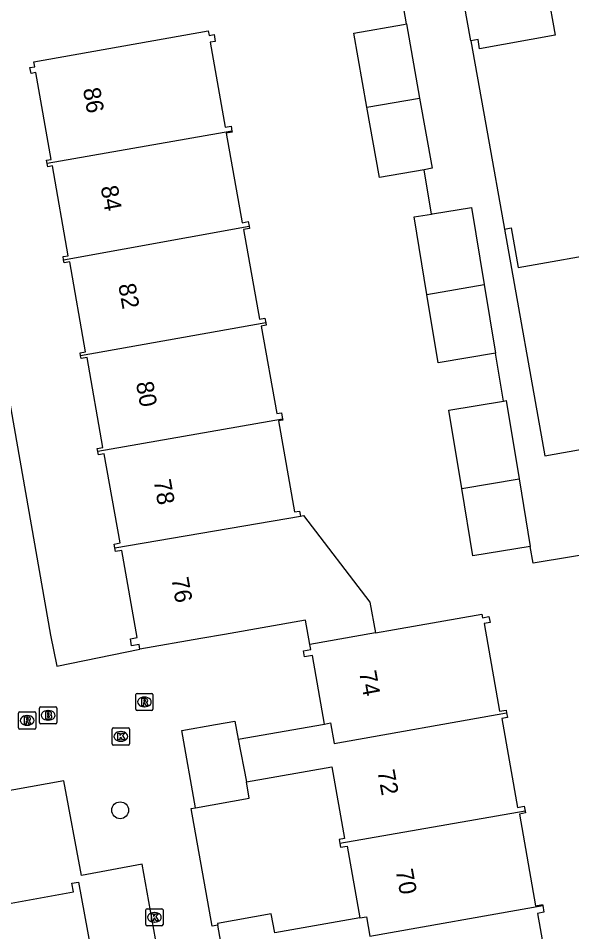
# Model space of a CAD drawing. Extents: x 157793 to 159380, y 380882 to 382313.
# Drawn here: x 158380 to 158412.2, y 381373.4 to 381426.5 of the extents above; entities that cross this region are included whole.
import ezdxf

# ---------------------------------------------------------------- set-up
doc = ezdxf.new("R2010")
doc.units = 0
for name, color, linetype in [('IMGEO_Boom', 7, 'Continuous'), ('IMGEO_Brandkraan', 7, 'Continuous'), ('IMGEO_Kolk', 7, 'Continuous'), ('IMGEO_Pand', 7, 'Continuous'), ('IMGEO_Pand_nummerreeks', 7, 'Continuous'), ('IMGEO_Rioolput', 7, 'Continuous'), ('IMGEO_Voetpad_open', 7, 'Continuous')]:
    doc.layers.add(name, color=color, linetype=linetype)

msp = doc.modelspace()

# ---------------------------------------------------------------- linework, layer by layer
at = {"layer": 'IMGEO_Boom'}
msp.add_circle((158385.911, 381380.479), 0.489, dxfattribs=at)
at = {"layer": 'IMGEO_Brandkraan'}
for p, q in [((158381.221, 381385.571), (158381.221, 381386.423)), ((158381.296, 381386.497), (158382.148, 381386.497)), ((158381.709, 381386.277), (158381.734, 381386.277)), ((158382.222, 381386.423), (158382.222, 381385.571)), ((158381.732, 381385.717), (158381.707, 381385.717)), ((158382.148, 381385.497), (158381.296, 381385.497))]:
    msp.add_line(p, q, dxfattribs=at)
for points in [[(158381.221, 381385.571), (158381.221, 381386.423)], [(158381.296, 381386.497), (158382.148, 381386.497)], [(158381.569, 381386.197), (158381.569, 381385.797), (158381.782, 381385.797)], [(158381.8, 381386.197), (158381.569, 381386.197)], [(158381.748, 381386.116), (158381.694, 381386.116), (158381.694, 381386.04)], [(158382.222, 381386.423), (158382.222, 381385.571)], [(158381.694, 381386.04), (158381.747, 381386.04)], [(158381.756, 381385.964), (158381.694, 381385.964), (158381.694, 381385.883)], [(158381.694, 381385.883), (158381.756, 381385.883)], [(158382.148, 381385.497), (158381.296, 381385.497)]]:
    msp.add_lwpolyline(points, dxfattribs=at)
for centre, radius, start, end in [((158381.298, 381386.421), 0.0765, 91.552, 178.448), ((158381.298, 381386.421), 0.0765, 91.552, 178.448), ((158381.749, 381386.078), 0.0379, 267.8285, 90.9355), ((158381.804, 381386.052), 0.145, 59.4692, 91.5367), ((158381.829, 381386.099), 0.0922, 285.5137, 58.1501), ((158382.146, 381386.421), 0.0765, 1.552, 88.448), ((158382.146, 381386.421), 0.0765, 1.552, 88.448), ((158381.757, 381385.923), 0.0404, 269.8759, 90.5077), ((158381.788, 381386.048), 0.251, 268.6676, 293.5347), ((158381.834, 381385.907), 0.105, 301.3115, 78.989), ((158381.298, 381385.573), 0.0765, 181.552, 268.448), ((158381.298, 381385.573), 0.0765, 181.552, 268.448), ((158382.146, 381385.573), 0.0765, 271.552, 358.448), ((158382.146, 381385.573), 0.0765, 271.552, 358.448)]:
    msp.add_arc(centre, radius, start, end, dxfattribs=at)
for centre, major_axis, ratio, start_param, end_param in [((158381.708, 381385.997), (-0.387, 0.002), 0.722429, 4.712389, 7.853982), ((158381.733, 381385.997), (-0.39, 0.002), 0.717154, 1.570796, 4.712389)]:
    msp.add_ellipse(centre, major_axis=major_axis, ratio=ratio, start_param=start_param, end_param=end_param, dxfattribs=at)
at = {"layer": 'IMGEO_Kolk'}
for p, q in [((158385.45, 381384.343), (158385.45, 381385.195)), ((158385.525, 381385.269), (158386.377, 381385.269)), ((158385.938, 381385.049), (158385.963, 381385.049)), ((158386.451, 381385.195), (158386.451, 381384.343)), ((158386.377, 381384.269), (158385.525, 381384.269)), ((158385.961, 381384.489), (158385.936, 381384.489)), ((158387.405, 381373.829), (158387.405, 381374.681)), ((158387.48, 381374.755), (158388.332, 381374.755)), ((158387.893, 381374.535), (158387.918, 381374.535)), ((158388.406, 381374.681), (158388.406, 381373.829)), ((158387.916, 381373.975), (158387.891, 381373.975)), ((158388.332, 381373.755), (158387.48, 381373.755))]:
    msp.add_line(p, q, dxfattribs=at)
for points in [[(158385.45, 381384.343), (158385.45, 381385.195)], [(158385.525, 381385.269), (158386.377, 381385.269)], [(158386.451, 381385.195), (158386.451, 381384.343)], [(158385.771, 381384.969), (158385.894, 381384.969), (158385.894, 381384.818), (158386.024, 381384.969), (158386.188, 381384.969), (158386.042, 381384.818), (158386.195, 381384.569), (158386.043, 381384.569), (158385.958, 381384.733), (158385.894, 381384.666), (158385.894, 381384.569), (158385.771, 381384.569), (158385.771, 381384.969)], [(158386.377, 381384.269), (158385.525, 381384.269)], [(158387.405, 381373.829), (158387.405, 381374.681)], [(158387.48, 381374.755), (158388.332, 381374.755)], [(158387.726, 381374.455), (158387.849, 381374.455), (158387.849, 381374.304), (158387.979, 381374.455), (158388.143, 381374.455), (158387.997, 381374.304), (158388.15, 381374.055), (158387.998, 381374.055), (158387.913, 381374.219), (158387.849, 381374.152), (158387.849, 381374.055), (158387.726, 381374.055), (158387.726, 381374.455)], [(158388.406, 381374.681), (158388.406, 381373.829)], [(158388.332, 381373.755), (158387.48, 381373.755)]]:
    msp.add_lwpolyline(points, dxfattribs=at)
for centre, start, end in [((158385.527, 381385.193), 91.552, 178.448), ((158385.527, 381385.193), 91.552, 178.448), ((158386.375, 381385.193), 1.552, 88.448), ((158386.375, 381385.193), 1.552, 88.448), ((158385.527, 381384.345), 181.552, 268.448), ((158385.527, 381384.345), 181.552, 268.448), ((158386.375, 381384.345), 271.552, 358.448), ((158386.375, 381384.345), 271.552, 358.448), ((158387.482, 381374.679), 91.552, 178.448), ((158387.482, 381374.679), 91.552, 178.448), ((158388.33, 381374.679), 1.552, 88.448), ((158388.33, 381374.679), 1.552, 88.448), ((158387.482, 381373.831), 181.552, 268.448), ((158387.482, 381373.831), 181.552, 268.448), ((158388.33, 381373.831), 271.552, 358.448), ((158388.33, 381373.831), 271.552, 358.448)]:
    msp.add_arc(centre, 0.0765, start, end, dxfattribs=at)
for centre, major_axis, ratio, start_param, end_param in [((158385.937, 381384.769), (-0.387, 0.002), 0.722429, 4.712389, 7.853982), ((158385.962, 381384.769), (-0.39, 0.002), 0.717154, 1.570796, 4.712389), ((158387.892, 381374.255), (-0.387, 0.002), 0.722429, 4.712389, 7.853982), ((158387.917, 381374.255), (-0.39, 0.002), 0.717154, 1.570796, 4.712389)]:
    msp.add_ellipse(centre, major_axis=major_axis, ratio=ratio, start_param=start_param, end_param=end_param, dxfattribs=at)
at = {"layer": 'IMGEO_Pand'}
for points in [[(158410.323, 381430.524), (158411.216, 381425.529), (158406.827, 381424.744), (158406.731, 381425.281), (158406.31, 381425.206)], [(158400.269, 381421.344), (158399.508, 381425.651), (158402.397, 381426.162), (158402.574, 381426.193)], [(158402.574, 381426.193), (158403.335, 381421.883)], [(158381.668, 381418.075), (158381.635, 381418.26), (158381.9, 381418.306), (158381.007, 381423.363), (158380.726, 381423.313), (158380.666, 381423.652), (158380.949, 381423.702), (158380.898, 381423.987), (158391.038, 381425.778), (158391.083, 381425.525), (158391.374, 381425.576), (158391.445, 381425.174), (158391.155, 381425.122), (158392.028, 381420.18), (158392.362, 381420.239), (158392.411, 381419.963)], [(158406.31, 381425.206), (158407.278, 381419.793), (158408.266, 381414.262)], [(158400.269, 381421.344), (158403.335, 381421.883)], [(158403.335, 381421.883), (158404.057, 381417.798), (158403.598, 381417.717)], [(158403.598, 381417.717), (158400.991, 381417.256), (158400.269, 381421.344)], [(158392.411, 381419.963), (158381.668, 381418.075)], [(158392.411, 381419.963), (158392.423, 381419.894), (158392.087, 381419.835), (158393.006, 381414.633), (158393.366, 381414.697), (158393.414, 381414.429)], [(158382.623, 381412.48), (158382.591, 381412.66), (158382.889, 381412.713), (158381.967, 381417.935), (158381.701, 381417.888), (158381.668, 381418.075)], [(158404.022, 381415.138), (158404.088, 381415.149), (158406.354, 381415.522), (158407.091, 381411.048)], [(158403.754, 381410.459), (158403.011, 381414.972), (158404.022, 381415.138)], [(158382.623, 381412.48), (158393.414, 381414.429)], [(158393.414, 381414.429), (158393.438, 381414.292), (158393.096, 381414.231), (158394.015, 381409.03), (158394.334, 381409.086), (158394.384, 381408.805)], [(158408.266, 381414.262), (158408.662, 381414.333), (158409.075, 381412.023), (158414.559, 381413.003)], [(158383.614, 381406.904), (158383.583, 381407.077), (158383.904, 381407.134), (158382.981, 381412.36), (158382.654, 381412.302), (158382.623, 381412.48)], [(158403.754, 381410.459), (158407.091, 381411.048)], [(158407.091, 381411.048), (158407.751, 381407.041)], [(158407.751, 381407.041), (158404.408, 381406.49), (158403.754, 381410.459)], [(158394.384, 381408.805), (158383.614, 381406.904)], [(158394.384, 381408.805), (158394.406, 381408.678), (158394.123, 381408.628), (158395.023, 381403.537), (158395.295, 381403.585), (158395.36, 381403.217)], [(158384.617, 381401.33), (158384.584, 381401.515), (158384.906, 381401.572), (158383.984, 381406.793), (158383.644, 381406.733), (158383.614, 381406.904)], [(158405.784, 381399.177), (158405.032, 381403.744), (158408.207, 381404.266)], [(158408.207, 381404.266), (158408.375, 381404.294), (158409.124, 381399.747)], [(158395.36, 381403.217), (158384.617, 381401.33)], [(158395.36, 381403.217), (158395.371, 381403.157), (158395.121, 381403.113), (158396.056, 381397.822), (158396.352, 381397.875), (158396.405, 381397.577)], [(158385.607, 381395.735), (158385.568, 381395.956), (158385.903, 381396.015), (158384.987, 381401.204), (158384.65, 381401.144), (158384.617, 381401.33)], [(158405.784, 381399.177), (158409.124, 381399.747)], [(158409.124, 381399.747), (158409.772, 381395.813)], [(158409.772, 381395.813), (158406.429, 381395.262), (158405.784, 381399.177)], [(158385.607, 381395.735), (158396.405, 381397.577)], [(158396.405, 381397.577), (158396.576, 381397.607), (158400.447, 381392.573), (158400.761, 381390.791)], [(158387.065, 381389.835), (158387.016, 381390.113), (158386.576, 381390.035), (158386.504, 381390.442), (158386.905, 381390.513), (158386.01, 381395.58), (158385.646, 381395.515), (158385.607, 381395.735)], [(158396.949, 381390.117), (158396.698, 381391.537), (158391.989, 381390.705), (158390.596, 381390.459), (158387.065, 381389.835)], [(158400.761, 381390.791), (158401.873, 381390.987), (158406.957, 381391.885), (158406.995, 381391.669), (158407.37, 381391.735), (158407.431, 381391.387), (158407.086, 381391.326), (158407.985, 381386.237), (158408.361, 381386.303), (158408.389, 381386.142)], [(158400.761, 381390.791), (158396.949, 381390.117)], [(158397.798, 381385.49), (158397.094, 381389.475), (158396.637, 381389.394), (158396.575, 381389.748), (158397.001, 381389.823), (158396.949, 381390.117)], [(158397.798, 381385.49), (158398.147, 381385.552), (158398.366, 381384.369), (158408.389, 381386.142)], [(158408.389, 381386.142), (158408.438, 381385.867), (158408.109, 381385.809), (158409.02, 381380.647), (158409.425, 381380.718), (158409.475, 381380.43)], [(158390.299, 381380.625), (158389.505, 381385.119), (158391.453, 381385.463), (158392.591, 381385.664), (158392.778, 381384.603)], [(158392.778, 381384.603), (158397.798, 381385.49)], [(158392.778, 381384.603), (158393.256, 381382.134)], [(158393.256, 381382.134), (158398.228, 381383.012), (158398.965, 381378.839), (158398.648, 381378.783), (158398.688, 381378.555)], [(158390.299, 381380.625), (158393.425, 381381.178), (158393.256, 381382.134)], [(158378.738, 381381.484), (158378.983, 381380.14), (158378.017, 381379.963), (158378.668, 381376.395), (158378.931, 381374.956), (158383.201, 381375.735), (158383.109, 381376.239), (158383.488, 381376.308), (158384.184, 381372.495)], [(158409.475, 381380.43), (158398.688, 381378.555)], [(158409.475, 381380.43), (158409.494, 381380.324), (158409.136, 381380.261), (158410.077, 381374.93), (158410.486, 381375.002), (158410.497, 381374.939)], [(158398.688, 381378.555), (158398.728, 381378.326), (158399.122, 381378.396), (158399.86, 381374.222)], [(158394.902, 381373.346), (158394.706, 381374.458), (158391.577, 381373.905), (158391.595, 381373.803)], [(158399.86, 381374.222), (158400.235, 381374.288), (158400.443, 381373.159), (158410.497, 381374.939)], [(158410.497, 381374.939), (158410.566, 381374.547), (158410.2, 381374.482), (158411.086, 381369.464), (158411.46, 381369.53), (158411.54, 381369.079), (158411.232, 381369.024), (158411.264, 381368.847), (158408.245, 381368.314)], [(158399.86, 381374.222), (158394.902, 381373.346)], [(158391.908, 381372.031), (158391.595, 381373.803)]]:
    msp.add_lwpolyline(points, dxfattribs=at)
at = {"layer": 'IMGEO_Rioolput'}
for p, q in [((158386.819, 381386.349), (158386.819, 381387.201)), ((158386.894, 381387.275), (158387.746, 381387.275)), ((158387.82, 381387.201), (158387.82, 381386.349)), ((158387.307, 381387.055), (158387.332, 381387.055)), ((158379.999, 381385.274), (158379.999, 381386.126)), ((158380.074, 381386.2), (158380.926, 381386.2)), ((158381, 381386.126), (158381, 381385.274)), ((158387.746, 381386.275), (158386.894, 381386.275)), ((158387.33, 381386.495), (158387.305, 381386.495)), ((158380.487, 381385.98), (158380.512, 381385.98)), ((158380.926, 381385.2), (158380.074, 381385.2)), ((158380.51, 381385.42), (158380.485, 381385.42))]:
    msp.add_line(p, q, dxfattribs=at)
for points in [[(158386.819, 381386.349), (158386.819, 381387.201)], [(158386.894, 381387.275), (158387.746, 381387.275)], [(158387.82, 381387.201), (158387.82, 381386.349)], [(158387.408, 381386.973), (158387.156, 381386.975), (158387.156, 381386.575)], [(158387.156, 381386.575), (158387.28, 381386.575), (158387.28, 381386.737), (158387.291, 381386.737)], [(158387.334, 381386.894), (158387.28, 381386.894), (158387.28, 381386.813)], [(158387.28, 381386.813), (158387.332, 381386.813)], [(158387.338, 381386.708), (158387.409, 381386.575), (158387.549, 381386.575), (158387.484, 381386.701)], [(158379.999, 381385.274), (158379.999, 381386.126)], [(158380.074, 381386.2), (158380.926, 381386.2)], [(158381, 381386.126), (158381, 381385.274)], [(158387.746, 381386.275), (158386.894, 381386.275)], [(158380.588, 381385.898), (158380.336, 381385.9), (158380.336, 381385.5)], [(158380.336, 381385.5), (158380.46, 381385.5), (158380.46, 381385.662), (158380.471, 381385.662)], [(158380.514, 381385.819), (158380.46, 381385.819), (158380.46, 381385.738)], [(158380.46, 381385.738), (158380.512, 381385.738)], [(158380.518, 381385.633), (158380.589, 381385.5), (158380.729, 381385.5), (158380.664, 381385.626)], [(158380.926, 381385.2), (158380.074, 381385.2)]]:
    msp.add_lwpolyline(points, dxfattribs=at)
for centre, radius, start, end in [((158386.896, 381387.199), 0.0765, 91.552, 178.448), ((158386.896, 381387.199), 0.0765, 91.552, 178.448), ((158387.744, 381387.199), 0.0765, 1.552, 88.448), ((158387.744, 381387.199), 0.0765, 1.552, 88.448), ((158387.29, 381386.684), 0.0533, 26.0293, 88.6989), ((158387.316, 381387.002), 0.19, 274.7715, 282.9687), ((158387.34, 381386.798), 0.0964, 77.0061, 93.1865), ((158387.354, 381386.855), 0.0378, 276.6634, 79.6772), ((158387.407, 381386.863), 0.109, 350.3612, 89.416), ((158387.405, 381386.863), 0.112, 277.5842, 350.9817), ((158387.389, 381386.648), 0.108, 29.5134, 73.7905), ((158380.076, 381386.124), 0.0765, 91.552, 178.448), ((158380.076, 381386.124), 0.0765, 91.552, 178.448), ((158380.924, 381386.124), 0.0765, 1.552, 88.448), ((158380.924, 381386.124), 0.0765, 1.552, 88.448), ((158386.896, 381386.351), 0.0765, 181.552, 268.448), ((158386.896, 381386.351), 0.0765, 181.552, 268.448), ((158387.744, 381386.351), 0.0765, 271.552, 358.448), ((158387.744, 381386.351), 0.0765, 271.552, 358.448), ((158380.47, 381385.609), 0.0533, 26.0293, 88.6989), ((158380.496, 381385.927), 0.19, 274.7715, 282.9687), ((158380.52, 381385.723), 0.0964, 77.0061, 93.1865), ((158380.534, 381385.78), 0.0378, 276.6634, 79.6772), ((158380.587, 381385.788), 0.109, 350.3612, 89.416), ((158380.585, 381385.788), 0.112, 277.5842, 350.9817), ((158380.569, 381385.573), 0.108, 29.5134, 73.7905), ((158380.076, 381385.276), 0.0765, 181.552, 268.448), ((158380.076, 381385.276), 0.0765, 181.552, 268.448), ((158380.924, 381385.276), 0.0765, 271.552, 358.448), ((158380.924, 381385.276), 0.0765, 271.552, 358.448)]:
    msp.add_arc(centre, radius, start, end, dxfattribs=at)
for centre, major_axis, ratio, start_param, end_param in [((158387.306, 381386.775), (-0.387, 0.002), 0.722429, 4.712389, 7.853982), ((158387.331, 381386.775), (-0.39, 0.002), 0.717154, 1.570796, 4.712389), ((158380.486, 381385.7), (-0.387, 0.002), 0.722429, 4.712389, 7.853982), ((158380.511, 381385.7), (-0.39, 0.002), 0.717154, 1.570796, 4.712389)]:
    msp.add_ellipse(centre, major_axis=major_axis, ratio=ratio, start_param=start_param, end_param=end_param, dxfattribs=at)
at = {"layer": 'IMGEO_Voetpad_open'}
for points in [[(158406.31, 381425.206), (158405.232, 381431.245)], [(158402.574, 381426.193), (158401.802, 381430.651)], [(158375.901, 381424.404), (158378.266, 381411.001), (158381.858, 381390.651), (158382.22, 381388.857), (158387.065, 381389.835)], [(158404.022, 381415.138), (158403.598, 381417.717)], [(158408.266, 381414.262), (158410.621, 381401.079), (158419.211, 381402.615), (158435.843, 381405.589), (158446.157, 381407.433), (158457.444, 381409.451)], [(158408.207, 381404.266), (158407.751, 381407.041)], [(158425.473, 381374.444), (158423.856, 381383.494), (158422.382, 381391.739), (158421.482, 381396.777), (158418.518, 381396.255), (158409.932, 381394.841), (158409.772, 381395.813)], [(158388.26, 381371.381), (158387.185, 381377.337), (158383.667, 381376.696), (158382.643, 381382.19), (158378.738, 381381.484)], [(158391.595, 381373.803), (158391.259, 381373.743), (158390.046, 381380.58), (158390.299, 381380.625)]]:
    msp.add_lwpolyline(points, dxfattribs=at)

# ---------------------------------------------------------------- texts
at = {"layer": 'IMGEO_Pand_nummerreeks'}
for s, rotation, p in [('86', 280.2359, (158383.745, 381422.402)), ('84', 280.2385, (158384.773, 381416.71)), ('82', 280.2359, (158385.8, 381411.021)), ('80', 280.2359, (158386.829, 381405.323)), ('78', 280.2385, (158387.857, 381399.631)), ('76', 280.2385, (158388.884, 381393.942)), ('74', 280.4677, (158399.809, 381388.507)), ('72', 280.4651, (158400.873, 381382.748)), ('70', 280.4677, (158401.938, 381376.98))]:
    msp.add_text(s, height=1, rotation=rotation, dxfattribs=at).set_placement(p)

doc.saveas('drawing.dxf')
